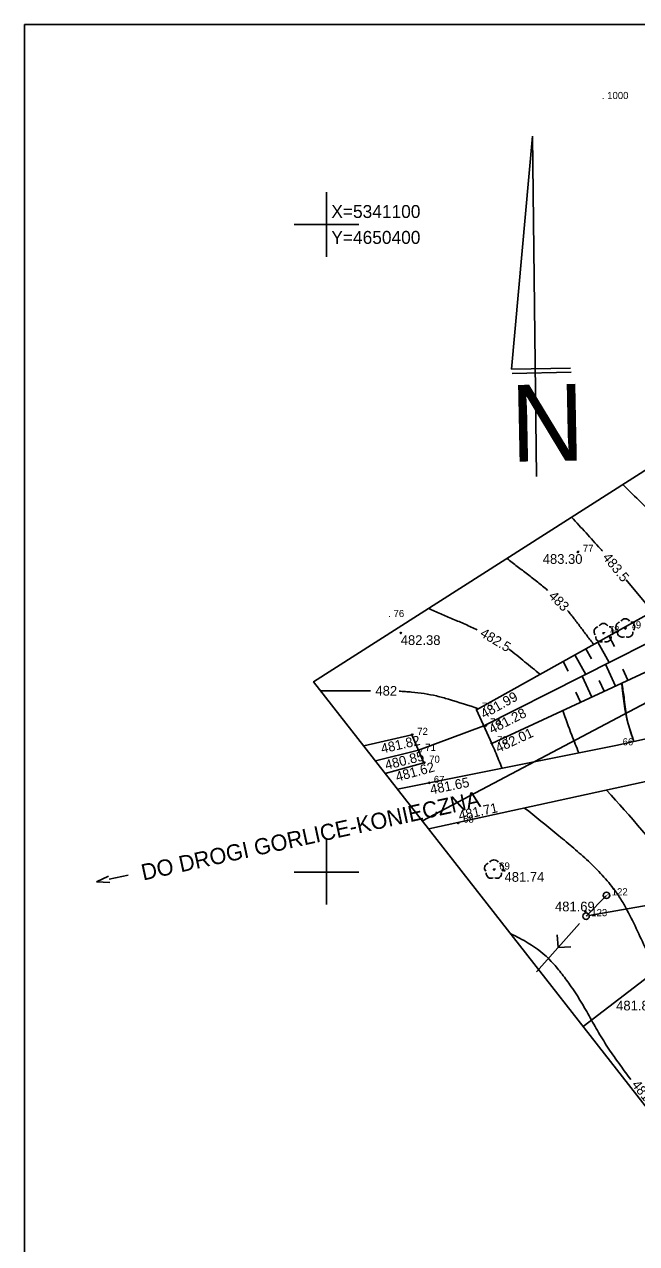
# Model space of a CAD drawing. Extents: x 4632591 to 4651113, y 5341001 to 5369868.
# Drawn here: x 4650982.1 to 4651012.5, y 5341031.3 to 5341091.9 of the extents above; entities that cross this region are included whole.
import ezdxf

# ---------------------------------------------------------------- set-up
doc = ezdxf.new("R2010")
doc.units = 0
doc.layers.add('Warstwa 1', color=7, linetype='Continuous')

msp = doc.modelspace()

# ---------------------------------------------------------------- linework, layer by layer
at = {"layer": 'Warstwa 1'}
for p, q in [((4651007.353, 5341086.341), (4651006.313, 5341074.76)), ((4651007.554, 5341069.438), (4651007.353, 5341086.341)), ((4650997.118, 5341080.347), (4650997.118, 5341083.566)), ((4650995.508, 5341081.956), (4650998.727, 5341081.956)), ((4651006.313, 5341074.76), (4651009.25, 5341074.818)), ((4651006.34, 5341074.549), (4651009.277, 5341074.608)), ((4651013.32, 5341062.717), (4651012.023, 5341064.295)), ((4651011.15, 5341061.506), (4651011.438, 5341060.989)), ((4651010.013, 5341060.871), (4651010.288, 5341060.377)), ((4651010.602, 5341061.2), (4651011.167, 5341060.188)), ((4651008.876, 5341060.236), (4651009.138, 5341059.766)), ((4651009.465, 5341060.565), (4651010.004, 5341059.6)), ((4651011.49, 5341059.02), (4651010.99, 5341060.099)), ((4651010.311, 5341058.474), (4651009.83, 5341059.512)), ((4651012.101, 5341059.303), (4651011.846, 5341059.853)), ((4651010.922, 5341058.757), (4651010.677, 5341059.287)), ((4650999.309, 5341058.787), (4650996.829, 5341058.781)), ((4651009.743, 5341058.212), (4651009.507, 5341058.721)), ((4651001.688, 5341055.84), (4651004.94, 5341057.04)), ((4651001.688, 5341055.84), (4650999.552, 5341055.302)), ((4650997.118, 5341048.155), (4650997.118, 5341051.374)), ((4650985.68, 5341049.283), (4650986.274, 5341049.578)), ((4650986.343, 5341049.263), (4650985.68, 5341049.283)), ((4650987.252, 5341049.627), (4650986.309, 5341049.421)), ((4650995.508, 5341049.764), (4650998.727, 5341049.764)), ((4651010.02, 5341047.582), (4651011.037, 5341048.618)), ((4651009.699, 5341047.221), (4651007.561, 5341044.815)), ((4651008.63, 5341046.018), (4651008.592, 5341046.66)), ((4651008.63, 5341046.018), (4651009.273, 5341046.056))]:
    msp.add_line(p, q, dxfattribs=at)
for points in [[(4650982.095, 5341091.899), (4650982.095, 5341000.802), (4651110.863, 5341000.802), (4651110.863, 5341091.899)], [(4651021.185, 5341027.659), (4650996.477, 5341059.231), (4651041.81, 5341088.134), (4651065.336, 5341062.46)]]:
    msp.add_lwpolyline(points, close=True, dxfattribs=at)
for points in [[(4651046.74, 5341082.754), (4651041.015, 5341078.074), (4651037.203, 5341075.808), (4651034.01, 5341073.477), (4651025.588, 5341069.279), (4651020.547, 5341067.161), (4651013.761, 5341062.963), (4651004.58, 5341057.838), (4651005.333, 5341056.171), (4651015.725, 5341060.98), (4651021.526, 5341064.56), (4651026.297, 5341067.167), (4651035.027, 5341070.084), (4651039.888, 5341071.127), (4651047.073, 5341074.649), (4651051.124, 5341077.97)], [(4651001.89, 5341052.314), (4651038.632, 5341071.719), (4651033.514, 5341077.211), (4651030.441, 5341080.885)], [(4651034.332, 5341071.623), (4651026.67, 5341068.069), (4651021.32, 5341065.886), (4651014.656, 5341061.952), (4651004.94, 5341057.04)], [(4651000.654, 5341053.894), (4651011.578, 5341056.074), (4651018.493, 5341057.626), (4651024.893, 5341060.613), (4651030.397, 5341064.402), (4651033.913, 5341061.476), (4651040.59, 5341054.522), (4651035.554, 5341050.846)], [(4651002.203, 5341051.915), (4651019.285, 5341055.649), (4651026.374, 5341057.561), (4651030.237, 5341058.656)], [(4651000.039, 5341054.679), (4651001.959, 5341055.205), (4651001.367, 5341056.589), (4650998.969, 5341056.047)], [(4651025.423, 5341054.018), (4651023.997, 5341052.925), (4651009.88, 5341042.105)], [(4651027.694, 5341050.681), (4651010.179, 5341047.61)]]:
    msp.add_lwpolyline(points, dxfattribs=at)
for centre, radius in [((4651009.616, 5341065.683), 0.029), ((4651011.971, 5341061.881), 0.029), ((4651000.809, 5341061.651), 0.029), ((4651010.889, 5341061.65), 0.029), ((4651004.594, 5341057.855), 0.029), ((4651005.047, 5341057.057), 0.029), ((4651001.366, 5341056.603), 0.029), ((4651001.698, 5341055.823), 0.029), ((4651005.329, 5341056.172), 0.029), ((4651001.978, 5341055.209), 0.029), ((4651002.231, 5341054.205), 0.029), ((4651003.659, 5341052.213), 0.029), ((4651005.443, 5341049.9), 0.029), ((4651005.97, 5341049.855), 0.029), ((4651011.037, 5341048.618), 0.161), ((4651010.02, 5341047.582), 0.161), ((4651009.987, 5341047.822), 0.029)]:
    msp.add_circle(centre, radius, dxfattribs=at)
for centre, start, end in [((4651010.66, 5341061.724), 102.14713, 221.85287), ((4651010.889, 5341061.891), 30.14713, 149.85287), ((4651011.119, 5341061.724), 318.14713, 77.85287), ((4651011.741, 5341061.956), 102.14713, 221.85287), ((4651011.971, 5341062.123), 30.14713, 149.85287), ((4651012.201, 5341061.956), 318.14713, 77.85287), ((4651010.747, 5341061.454), 174.14717, 293.85287), ((4651011.031, 5341061.454), 246.14713, 5.85287), ((4651011.829, 5341061.686), 174.14717, 293.85287), ((4651012.113, 5341061.686), 246.14713, 5.85287), ((4651005.213, 5341049.974), 102.14713, 221.85287), ((4651005.443, 5341050.141), 30.14713, 149.85287), ((4651005.672, 5341049.974), 318.14713, 77.85287), ((4651005.301, 5341049.704), 174.14717, 293.85287), ((4651005.584, 5341049.704), 246.14713, 5.85287)]:
    msp.add_arc(centre, 0.241, start, end, dxfattribs=at)
for points in [[(4651011.848, 5341069.031), (4651013.72, 5341067.216), (4651013.813, 5341067.128)], [(4651010.838, 5341065.728), (4651010.731, 5341065.846), (4651009.306, 5341067.41)], [(4651006.096, 5341065.364), (4651006.599, 5341064.965), (4651007.109, 5341064.575), (4651007.616, 5341064.181), (4651008.11, 5341063.774)], [(4651002.189, 5341062.872), (4651002.793, 5341062.604), (4651003.403, 5341062.347), (4651004.011, 5341062.086), (4651004.611, 5341061.811)], [(4651009.107, 5341062.767), (4651009.438, 5341062.354), (4651009.758, 5341061.931), (4651010.076, 5341061.506), (4651010.401, 5341061.088)], [(4651006.187, 5341060.853), (4651006.58, 5341060.546), (4651006.967, 5341060.23), (4651007.354, 5341059.914), (4651007.745, 5341059.605)], [(4651011.797, 5341059.162), (4651012.109, 5341057.147), (4651012.402, 5341056.259)], [(4651012.4, 5341056.258), (4651012.032, 5341057.507), (4651011.909, 5341058.472), (4651011.799, 5341059.163)], [(4651004.678, 5341057.893), (4651003.186, 5341058.362), (4651002.585, 5341058.524), (4651001.972, 5341058.64), (4651001.35, 5341058.718), (4651001.038, 5341058.745), (4651000.725, 5341058.764)], [(4651008.861, 5341057.803), (4651009.308, 5341056.583), (4651009.666, 5341055.692)], [(4651005.843, 5341054.929), (4651005.504, 5341055.771), (4651005.333, 5341056.171)], [(4651011.041, 5341053.847), (4651014.412, 5341049.765), (4651014.854, 5341049.039), (4651015.151, 5341048.226), (4651015.402, 5341047.385), (4651015.542, 5341046.971), (4651015.708, 5341046.572), (4651016.002, 5341045.947), (4651016.305, 5341045.328), (4651016.986, 5341044.12), (4651017.191, 5341043.809)], [(4651015.426, 5341041.812), (4651014.939, 5341042.577), (4651014.469, 5341043.353), (4651014.008, 5341044.134), (4651013.546, 5341044.915), (4651013.008, 5341045.93), (4651012.521, 5341046.972), (4651012.003, 5341047.998), (4651011.708, 5341048.491), (4651011.547, 5341048.73), (4651011.376, 5341048.963), (4651010.741, 5341049.709), (4651010.049, 5341050.395), (4651009.318, 5341051.04), (4651008.566, 5341051.66), (4651006.969, 5341052.957)], [(4651012.242, 5341039.46), (4651011.729, 5341040.165), (4651011.226, 5341040.878), (4651010.709, 5341041.692), (4651010.231, 5341042.528), (4651009.749, 5341043.363), (4651009.22, 5341044.174), (4651008.775, 5341044.771), (4651008.293, 5341045.338), (4651007.151, 5341046.244), (4651006.277, 5341046.709)]]:
    msp.add_spline(points, degree=3, dxfattribs=at)

# ---------------------------------------------------------------- texts
for s, height, p in [('. 1000', 0.3541, (4651010.812, 5341088.189)), ('. 1000', 0.3541, (4651010.812, 5341088.189)), ('. 1000', 0.3541, (4651010.812, 5341088.189)), ('. 1000', 0.3541, (4651010.812, 5341088.189)), (' X=5341100 ', 0.64384, (4650997.118, 5341082.278)), (' Y=4650400 ', 0.64384, (4650997.118, 5341080.991)), ('483.30', 0.4829, (4651007.869, 5341065.09)), ('. 77', 0.3541, (4651009.602, 5341065.687)), ('. 76', 0.3541, (4651000.189, 5341062.448)), ('. 78', 0.3541, (4651010.889, 5341061.65)), ('. 79', 0.3541, (4651011.971, 5341061.881)), ('482.38', 0.4829, (4651000.809, 5341061.059)), ('. 75', 0.3541, (4651004.58, 5341057.838)), ('. 74', 0.3541, (4651004.992, 5341057.053)), ('. 72', 0.3541, (4651001.367, 5341056.589)), ('. 73', 0.3541, (4651005.333, 5341056.171)), ('. 71', 0.3541, (4651001.766, 5341055.797)), ('. 66', 0.3541, (4651011.578, 5341056.074)), ('. 70', 0.3541, (4651001.959, 5341055.205)), ('. 67', 0.3541, (4651002.191, 5341054.2)), ('. 68', 0.3541, (4651003.646, 5341052.23)), ('. 69', 0.3541, (4651005.443, 5341049.9)), ('481.74', 0.4829, (4651005.97, 5341049.293)), ('. 122', 0.3541, (4651011.037, 5341048.618)), ('481.69', 0.4829, (4651008.477, 5341047.822)), ('. 123', 0.3541, (4651010.02, 5341047.582)), ('481.85', 0.4829, (4651011.52, 5341042.899))]:
    msp.add_text(s, height=height, dxfattribs=at).set_placement(p)
for s, height, rotation, p in [('N', 3.811, 1.1353, (4651006.299, 5341070.162)), ('483.5', 0.4829, 309.07145, (4651010.814, 5341065.399)), ('483', 0.4829, 314.91268, (4651008.128, 5341063.454)), ('482.5', 0.4829, 328.97829, (4651004.713, 5341061.521)), ('482', 0.4829, 359.26578, (4650999.547, 5341058.551)), ('481.99', 0.4829, 29.17046, (4651004.951, 5341057.383)), ('481.28', 0.4829, 26.82309, (4651005.343, 5341056.627)), ('481.82', 0.4829, 12.7337, (4650999.88, 5341055.666)), ('482.01', 0.4829, 24.83589, (4651005.656, 5341055.694)), ('480.85', 0.4829, 14.12277, (4651000.091, 5341054.849)), ('481.62', 0.4829, 15.30365, (4651000.628, 5341054.267)), ('481.65', 0.4829, 11.28726, (4651002.316, 5341053.631)), ('DO DROGI GORLICE-KONIECZNA', 0.8048, 12.33135, (4650988.004, 5341049.351)), ('481.71', 0.4829, 12.33135, (4651003.737, 5341052.334)), ('481.5', 0.4829, 307.88878, (4651012.265, 5341039.202))]:
    msp.add_text(s, height=height, rotation=rotation, dxfattribs=at).set_placement(p)

doc.saveas('drawing.dxf')
